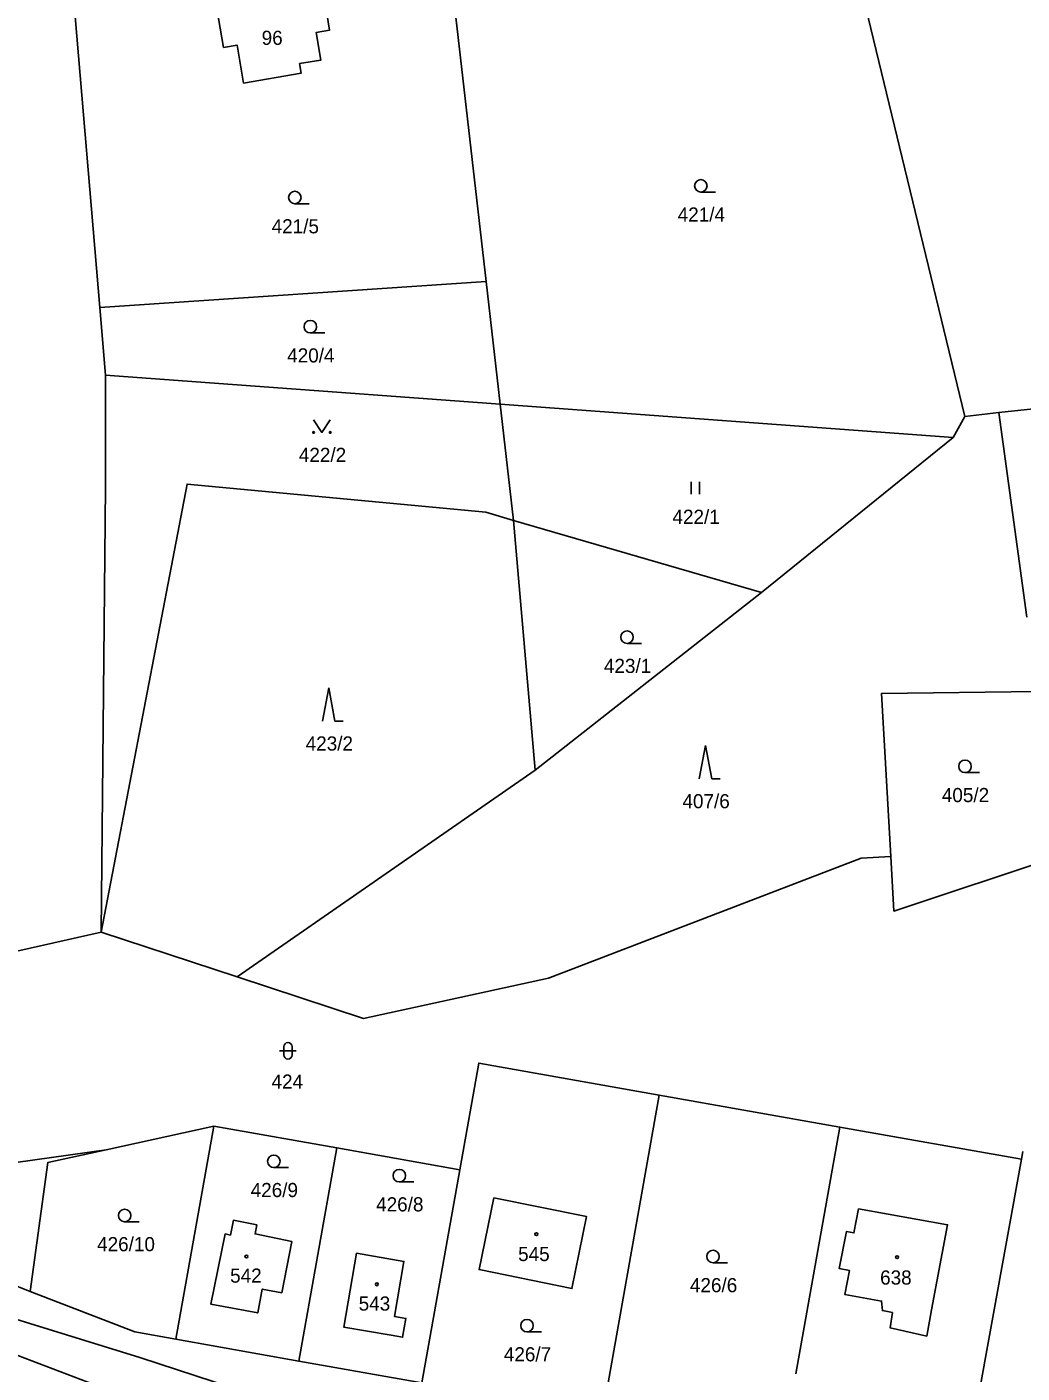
# Model space of a CAD drawing. Extents: x -725728 to -720881, y -1068679 to -1063504.
# Drawn here: x -724156.4 to -724036.7, y -1067350.1 to -1067188.2 of the extents above; entities that cross this region are included whole.
import ezdxf

# ---------------------------------------------------------------- set-up
doc = ezdxf.new("R2010")
doc.units = 0
for name, color, linetype in [('Hranice parcel', 7, 'Continuous'), ('Parcelní čísla', 7, 'Continuous'), ('Značky budov', 7, 'Continuous'), ('Značky kultur', 7, 'Continuous')]:
    doc.layers.add(name, color=color, linetype=linetype)

# ---------------------------------------------------------------- blocks, each defined once
blk = doc.blocks.new('4.02_4')
at = {"layer": 'Značky budov'}
blk.add_circle((-0.001, 0), 0.0175, dxfattribs=at)
blk = doc.blocks.new('4.02_3')
at = {"layer": 'Značky budov'}
blk.add_circle((-0.001, 0), 0.0175, dxfattribs=at)
blk = doc.blocks.new('3.04_3')
at = {"layer": 'Značky kultur'}
blk.add_line((0.001, 0), (0.176, 0), dxfattribs=at)
blk.add_circle((0.001, 0.075), 0.075, dxfattribs=at)
blk = doc.blocks.new('3.04_2')
at = {"layer": 'Značky kultur'}
blk.add_line((0.001, 0), (0.176, 0), dxfattribs=at)
blk.add_circle((0.001, 0.075), 0.075, dxfattribs=at)
blk = doc.blocks.new('3.06_2')
at = {"layer": 'Značky kultur'}
for p, q in [((-0.051, 0), (-0.051, 0.15)), ((0.049, 0), (0.049, 0.15))]:
    blk.add_line(p, q, dxfattribs=at)
blk = doc.blocks.new('3.14_1')
at = {"layer": 'Značky kultur'}
blk.add_lwpolyline([(-0.1, 0.15), (0, 0), (0.1, 0.15)], dxfattribs=at)
for centre in [(-0.1, 0), (0.1, 0)]:
    blk.add_circle(centre, 0.01, dxfattribs=at)
blk = doc.blocks.new('3.08_1')
at = {"layer": 'Značky kultur'}
for p, q in [((0, 0.4), (-0.075, 0)), ((0.075, 0), (0, 0.4)), ((0.075, 0), (0.175, 0))]:
    blk.add_line(p, q, dxfattribs=at)
blk = doc.blocks.new('3.16_2')
at = {"layer": 'Značky kultur'}
for p, q in [((-0.1, 0.1), (0.1, 0.1)), ((-0.05, 0.15), (-0.05, 0.05)), ((0.05, 0.05), (0.05, 0.15))]:
    blk.add_line(p, q, dxfattribs=at)
for centre, start, end in [((0, 0.15), 0, 180), ((0, 0.05), 180, 359.9879)]:
    blk.add_arc(centre, 0.05, start, end, dxfattribs=at)
blk = doc.blocks.new('3.08_2')
at = {"layer": 'Značky kultur'}
for p, q in [((0, 0.4), (-0.075, 0)), ((0.075, 0), (0, 0.4)), ((0.075, 0), (0.175, 0))]:
    blk.add_line(p, q, dxfattribs=at)

msp = doc.modelspace()

# ---------------------------------------------------------------- linework, layer by layer
at = {"layer": 'Hranice parcel'}
for p, q in [((-724106.26, -1067174.37), (-724101.17, -1067218.83)), ((-724058.26, -1067174.62), (-724043.61, -1067235.06)), ((-724147.6, -1067221.96), (-724150.93, -1067182.46)), ((-724101.17, -1067218.83), (-724147.6, -1067221.96)), ((-724099.48, -1067233.6), (-724101.17, -1067218.83)), ((-724146.92, -1067230.1), (-724147.6, -1067221.96)), ((-724146.92, -1067230.1), (-724099.48, -1067233.6)), ((-724039.53, -1067234.61), (-724007.94, -1067231.11)), ((-724099.48, -1067233.6), (-724097.88, -1067247.56)), ((-724099.48, -1067233.6), (-724045.03, -1067237.61)), ((-724043.61, -1067235.06), (-724045.03, -1067237.61)), ((-724043.61, -1067235.06), (-724039.53, -1067234.61)), ((-724036.17, -1067259.2), (-724039.53, -1067234.61)), ((-724045.03, -1067237.61), (-724068.07, -1067256.23)), ((-724097.88, -1067247.56), (-724068.07, -1067256.23)), ((-724097.88, -1067247.56), (-724095.27, -1067277.58)), ((-724068.07, -1067256.23), (-724095.27, -1067277.58)), ((-724095.27, -1067277.58), (-724131.09, -1067302.46)), ((-724147.44, -1067297.08), (-724131.09, -1067302.46)), ((-724080.36, -1067316.67), (-724087.19, -1067355.12)), ((-724080.36, -1067316.67), (-724058.67, -1067320.52)), ((-724146.86, -1067323.24), (-724133.91, -1067320.39)), ((-724133.91, -1067320.39), (-724138.46, -1067346.02)), ((-724133.91, -1067320.39), (-724119.12, -1067323.01)), ((-724058.67, -1067320.52), (-724063.93, -1067350.19)), ((-724058.67, -1067320.52), (-724036.83, -1067324.39)), ((-724185.48, -1067328.64), (-724146.86, -1067323.24)), ((-724119.12, -1067323.01), (-724123.67, -1067348.65)), ((-724119.12, -1067323.01), (-724104.33, -1067325.64)), ((-724036.83, -1067324.39), (-724036.66, -1067323.43)), ((-724036.83, -1067324.39), (-724043.8, -1067362.82)), ((-724104.33, -1067325.64), (-724108.88, -1067351.27)), ((-724185.48, -1067328.64), (-724155.99, -1067340.27)), ((-724138.46, -1067346.02), (-724123.67, -1067348.65)), ((-724144.82, -1067352.77), (-724160.72, -1067346.75)), ((-724123.67, -1067348.65), (-724108.88, -1067351.27))]:
    msp.add_line(p, q, dxfattribs=at)
for points in [[(-724125.41, -1067177.84), (-724125.12, -1067179.26), (-724124.23, -1067184.59), (-724125.05, -1067184.74), (-724125.43, -1067182.26), (-724132.31, -1067183.4), (-724131.9, -1067185.77), (-724133.52, -1067186.05), (-724132.72, -1067190.7), (-724131.1, -1067190.42), (-724130.32, -1067194.98), (-724123.39, -1067193.79), (-724123.59, -1067192.65), (-724121.02, -1067192.21), (-724121.59, -1067188.89), (-724119.98, -1067188.61), (-724120.68, -1067184.33), (-724120.73, -1067184), (-724121.59, -1067178.71), (-724121.84, -1067177.19)], [(-724147.44, -1067297.08), (-724146.92, -1067243.58), (-724146.92, -1067230.1)], [(-724147.44, -1067297.08), (-724137.11, -1067243.19), (-724101.22, -1067246.59), (-724097.88, -1067247.56)], [(-724034.95, -1067268.14), (-724053.64, -1067268.36), (-724052.52, -1067287.96)], [(-724131.09, -1067302.46), (-724115.9, -1067307.45), (-724093.69, -1067302.59), (-724056.09, -1067288.18), (-724052.52, -1067287.96)], [(-724052.52, -1067287.96), (-724052.14, -1067294.55), (-724032.27, -1067287.95)], [(-724193.8, -1067306.12), (-724170.26, -1067302.2), (-724147.44, -1067297.08)], [(-724104.33, -1067325.64), (-724102.06, -1067312.82), (-724080.36, -1067316.67)], [(-724155.99, -1067340.27), (-724153.86, -1067324.78), (-724146.86, -1067323.24)], [(-724018.75, -1067367.26), (-724044.28, -1067367.29), (-724124.91, -1067354.08), (-724142.81, -1067348.22), (-724171.47, -1067339.34), (-724191.42, -1067330.05)], [(-724100.26, -1067329.01), (-724089.1, -1067331.27), (-724090.85, -1067339.93), (-724102.01, -1067337.64), (-724100.26, -1067329.01)], [(-724052.3, -1067342.79), (-724053.53, -1067342.57), (-724053.63, -1067341.43), (-724058.05, -1067340.64), (-724057.49, -1067337.77), (-724058.73, -1067337.53), (-724057.86, -1067333.07), (-724056.96, -1067333.24), (-724056.4, -1067330.35), (-724045.7, -1067332.25), (-724047.64, -1067342.49), (-724048.2, -1067345.64), (-724052.62, -1067344.64), (-724052.3, -1067342.79)], [(-724132.55, -1067333.36), (-724131.9, -1067333.49), (-724131.54, -1067331.71), (-724128.73, -1067332.28), (-724128.95, -1067333.35), (-724124.53, -1067334.25), (-724125.73, -1067340.44), (-724128.07, -1067339.99), (-724128.62, -1067342.85), (-724134.27, -1067341.79), (-724132.55, -1067333.36)], [(-724112.58, -1067345.55), (-724118.26, -1067344.57), (-724116.73, -1067335.68), (-724111.05, -1067336.66), (-724112.19, -1067343.28), (-724110.81, -1067343.52), (-724111.2, -1067345.79), (-724112.58, -1067345.55)], [(-724155.99, -1067340.27), (-724143.39, -1067345.15), (-724138.46, -1067346.02)]]:
    msp.add_lwpolyline(points, dxfattribs=at)

# ---------------------------------------------------------------- block references
at = {"layer": 'Značky budov', "xscale": 10, "yscale": 10}
for name, p in [('4.02_4', (-724095.12, -1067333.39)), ('4.02_3', (-724129.97, -1067336.07)), ('4.02_4', (-724051.76, -1067336.15)), ('4.02_4', (-724114.29, -1067339.41))]:
    msp.add_blockref(name, p, dxfattribs=at)
at = {"layer": 'Značky kultur', "xscale": 10, "yscale": 10}
for name, p in [('3.04_2', (-724075.37, -1067208.09)), ('3.04_2', (-724124.18, -1067209.5)), ('3.04_2', (-724122.31, -1067225.03)), ('3.14_1', (-724120.91, -1067236.99)), ('3.06_2', (-724076, -1067244.43)), ('3.04_2', (-724084.24, -1067262.36)), ('3.08_1', (-724120.09, -1067271.69)), ('3.08_2', (-724074.8, -1067278.63)), ('3.04_3', (-724043.62, -1067277.89)), ('3.16_2', (-724124.99, -1067312.34)), ('3.04_3', (-724126.7, -1067325.38)), ('3.04_2', (-724111.62, -1067327.1)), ('3.04_3', (-724144.63, -1067331.89)), ('3.04_2', (-724073.9, -1067336.82)), ('3.04_3', (-724096.27, -1067345.13))]:
    msp.add_blockref(name, p, dxfattribs=at)

# ---------------------------------------------------------------- texts
at = {"layer": 'Parcelní čísla'}
for s, p in [('96', (-724128.15, -1067190.39)), ('421/4', (-724078.14, -1067211.64)), ('421/5', (-724126.95, -1067213.05)), ('420/4', (-724125.08, -1067228.58)), ('422/2', (-724123.68, -1067240.54)), ('422/1', (-724078.77, -1067247.98)), ('423/1', (-724087.01, -1067265.91)), ('423/2', (-724122.86, -1067275.24)), ('405/2', (-724046.39, -1067281.44)), ('407/6', (-724077.57, -1067282.18)), ('424', (-724126.96, -1067315.89)), ('426/9', (-724129.47, -1067328.93)), ('426/8', (-724114.39, -1067330.65)), ('426/10', (-724147.93, -1067335.44)), ('545', (-724097.32, -1067336.62)), ('542', (-724131.94, -1067339.22)), ('638', (-724053.81, -1067339.45)), ('426/6', (-724076.67, -1067340.37)), ('543', (-724116.49, -1067342.58)), ('426/7', (-724099.04, -1067348.68))]:
    msp.add_text(s, height=1.7, dxfattribs=at).set_placement(p)

doc.saveas('drawing.dxf')
